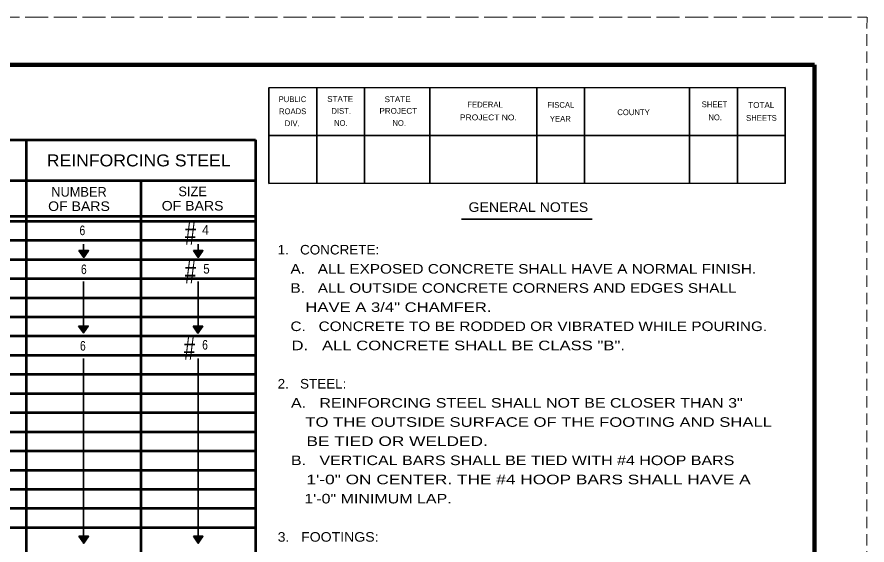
# Model space of a CAD drawing. Extents: x -560 to 120, y 26 to 466.
# Drawn here: x -57.5 to 120.2, y 355.5 to 465.8 of the extents above; entities that cross this region are included whole.
import ezdxf
from ezdxf.enums import TextEntityAlignment as Align

# ---------------------------------------------------------------- set-up
doc = ezdxf.new("R2010")
doc.units = 0
doc.header["$LTSCALE"] = 0.8
doc.linetypes.add('LONG_DASHED', pattern=[7.5, 6, -1.5])
doc.linetypes.add('MEDIUM_DASHED', pattern=[4.5, 3, -1.5])
doc.layers.add('1', color=7, linetype='Continuous', lineweight=53)
doc.layers.add('61', color=7, linetype='Continuous', lineweight=35)

msp = doc.modelspace()

# ---------------------------------------------------------------- linework, layer by layer
at = {"layer": '1', "linetype": 'MEDIUM_DASHED', "lineweight": 13}
msp.add_line((120.2391, 465.8427), (120.2191, 25.8227), dxfattribs=at)
at = {"layer": '1'}
for p, q in [((-127.5876, 440.21), (-7.5954, 440.21)), ((-55.5954, 440.21), (-55.5954, 267.21)), ((-7.5954, 440.21), (-7.5954, 267.21)), ((-127.5954, 431.71), (-7.5954, 431.71)), ((-31.5954, 431.71), (-31.5954, 267.21)), ((-267.5954, 424.21), (-7.6086, 424.21)), ((-267.5954, 423.21), (-7.6086, 423.21)), ((-267.5954, 419.21), (-7.6086, 419.21)), ((-267.5954, 415.21), (-7.6086, 415.21)), ((-267.5954, 411.21), (-7.6086, 411.21)), ((-267.5954, 407.21), (-7.6086, 407.21)), ((-267.5954, 403.21), (-7.6086, 403.21)), ((-267.5954, 399.21), (-7.6086, 399.21)), ((-267.5954, 395.21), (-7.6086, 395.21)), ((-267.5954, 391.21), (-7.6086, 391.21)), ((-267.5954, 387.21), (-7.6086, 387.21)), ((-267.5954, 383.21), (-7.6086, 383.21)), ((-267.5954, 379.21), (-7.6086, 379.21)), ((-267.5954, 375.21), (-7.6086, 375.21)), ((-267.5954, 371.21), (-7.6086, 371.21)), ((-267.5954, 367.21), (-7.6086, 367.21)), ((-267.5954, 363.21), (-7.6086, 363.21)), ((-267.5954, 359.21), (-7.6086, 359.21))]:
    msp.add_line(p, q, dxfattribs=at)
at = {"layer": '1', "lineweight": 35}
for p, q in [((35.464, 423.6132), (62.8017, 423.6132)), ((-43.5954, 418.4196), (-43.5954, 415.9432)), ((-19.5954, 418.4196), (-19.5954, 415.9432)), ((-43.5954, 410.5774), (-43.5954, 399.846)), ((-19.5954, 410.5774), (-19.5954, 399.846)), ((-43.5954, 394.4803), (-43.5954, 355.8888)), ((-19.5954, 394.4803), (-19.5954, 355.8888))]:
    msp.add_line(p, q, dxfattribs=at)
for points in [[(-44.5178, 417.0657), (-42.5178, 417.0657), (-43.5178, 415.6132)], [(-20.5897, 417.0657), (-18.5897, 417.0657), (-19.5897, 415.6132)], [(-44.5858, 401.2948), (-42.5858, 401.2948), (-43.5858, 399.8424)], [(-20.6576, 401.2268), (-18.6576, 401.2268), (-19.6576, 399.7744)], [(-44.5178, 357.381), (-42.5178, 357.381), (-43.5178, 355.9286)], [(-20.5896, 357.381), (-18.5896, 357.381), (-19.5896, 355.9286)]]:
    msp.add_lwpolyline(points, close=True, dxfattribs=at)
for points in [[(-44.3309, 416.9224), (-44.025, 416.9564), (-43.5492, 416.8545), (-43.2092, 416.9224), (-43.0733, 416.9224), (-42.8693, 416.9904), (-42.7334, 416.9564), (-43.3452, 416.8205), (-43.6171, 417.0584), (-43.5832, 416.8205), (-43.5832, 416.8885), (-43.2772, 416.9904), (-42.9033, 416.9904), (-42.9713, 416.9224), (-43.6851, 416.9564), (-43.957, 416.9224), (-44.1269, 416.8545), (-43.991, 416.7525), (-43.923, 416.6166), (-43.855, 416.4806), (-43.8211, 416.3787), (-43.7191, 416.2427), (-43.4132, 416.0048), (-43.4132, 415.8008), (-43.5152, 416.0048), (-43.5832, 416.1747), (-43.7191, 416.3447), (-43.855, 416.5146), (-44.059, 416.6845), (-44.1949, 416.9224), (-44.059, 416.7185), (-43.991, 416.4806), (-43.889, 416.3447), (-43.8211, 416.2767), (-43.6511, 416.1747), (-43.5492, 416.1067), (-43.4812, 415.9708), (-43.4472, 415.9367), (-43.5492, 415.9708), (-43.6511, 416.1407), (-43.6511, 415.9708), (-43.2772, 416.0727), (-42.7674, 416.9564), (-42.7334, 416.9564), (-42.7674, 416.8205), (-42.9033, 416.5826), (-43.0393, 416.3787), (-43.0733, 416.3787), (-43.2092, 416.1407), (-43.3113, 415.9367), (-43.4132, 415.8008), (-43.4812, 415.8008), (-42.6994, 416.9564), (-42.7334, 416.8545), (-42.6314, 416.9224), (-42.7674, 416.7525), (-42.9713, 416.5146), (-43.0733, 416.4466), (-43.2092, 416.2087), (-43.2772, 416.1747), (-43.3792, 416.3107), (-43.5152, 416.3107), (-43.6511, 416.3107), (-43.4132, 416.1067), (-43.4472, 416.2087), (-43.6171, 416.1067), (-43.2772, 416.5486), (-43.3452, 416.4126), (-43.3792, 416.3447), (-43.5152, 416.3447), (-43.6511, 416.4466), (-43.6851, 416.6505), (-43.7531, 416.7185), (-43.8211, 416.7865), (-43.4812, 416.8885), (-43.3452, 416.6845), (-43.3113, 416.7525), (-43.5832, 416.6166), (-43.4132, 416.6505), (-43.2092, 416.7865), (-43.1412, 416.7185), (-43.3792, 416.5146), (-43.3792, 416.7185), (-43.5152, 416.8545), (-43.8211, 416.7525), (-43.889, 416.3447), (-43.4812, 416.6845), (-43.3113, 416.6505), (-43.2092, 416.7185), (-43.1073, 416.8205), (-43.2432, 416.4806), (-43.2772, 416.2767), (-43.0393, 416.5826), (-43.2092, 416.5486), (-43.0053, 416.8205), (-43.1073, 416.6845), (-43.1412, 416.6505), (-43.3452, 416.4466), (-43.3792, 416.4806), (-43.4472, 416.6166), (-43.4812, 416.7865)], [(-43.4812, 416.7865), (-43.7191, 416.6166), (-43.5832, 416.5146), (-43.991, 416.7525), (-43.991, 416.8205), (-43.7871, 416.4806), (-43.4472, 416.5146), (-43.6171, 416.4126), (-43.4132, 416.4466), (-43.1073, 416.7525), (-42.9373, 416.7865), (-42.9373, 416.8205), (-43.0393, 416.6166), (-43.3452, 416.2427), (-43.4132, 415.9708), (-43.923, 416.7865), (-43.923, 416.9224), (-43.855, 416.7865), (-43.923, 416.3787), (-43.5492, 416.1747), (-43.6851, 415.8348), (-43.5152, 415.9027), (-43.6511, 416.3447), (-43.2092, 416.7865), (-43.5832, 416.6845)], [(-20.4028, 416.9224), (-20.0968, 416.9564), (-19.621, 416.8545), (-19.2811, 416.9224), (-19.1452, 416.9224), (-18.9412, 416.9904), (-18.8053, 416.9564), (-19.417, 416.8205), (-19.6889, 417.0584), (-19.655, 416.8205), (-19.655, 416.8885), (-19.3491, 416.9904), (-18.9752, 416.9904), (-19.0432, 416.9224), (-19.7569, 416.9564), (-20.0288, 416.9224), (-20.1988, 416.8545), (-20.0628, 416.7525), (-19.9948, 416.6166), (-19.9268, 416.4806), (-19.8929, 416.3787), (-19.7909, 416.2427), (-19.485, 416.0048), (-19.485, 415.8008), (-19.587, 416.0048), (-19.655, 416.1747), (-19.7909, 416.3447), (-19.9268, 416.5146), (-20.1308, 416.6845), (-20.2667, 416.9224), (-20.1308, 416.7185), (-20.0628, 416.4806), (-19.9608, 416.3447), (-19.8929, 416.2767), (-19.7229, 416.1747), (-19.621, 416.1067), (-19.553, 415.9708), (-19.519, 415.9367), (-19.621, 415.9708), (-19.7229, 416.1407), (-19.7229, 415.9708), (-19.3491, 416.0727), (-18.8392, 416.9564), (-18.8053, 416.9564), (-18.8392, 416.8205), (-18.9752, 416.5826), (-19.1112, 416.3787), (-19.1452, 416.3787), (-19.2811, 416.1407), (-19.3831, 415.9367), (-19.485, 415.8008), (-19.553, 415.8008), (-18.7712, 416.9564), (-18.8053, 416.8545), (-18.7033, 416.9224), (-18.8392, 416.7525), (-19.0432, 416.5146), (-19.1452, 416.4466), (-19.2811, 416.2087), (-19.3491, 416.1747), (-19.451, 416.3107), (-19.587, 416.3107), (-19.7229, 416.3107), (-19.485, 416.1067), (-19.519, 416.2087), (-19.6889, 416.1067), (-19.3491, 416.5486), (-19.417, 416.4126), (-19.451, 416.3447), (-19.587, 416.3447), (-19.7229, 416.4466), (-19.7569, 416.6505), (-19.8249, 416.7185), (-19.8929, 416.7865), (-19.553, 416.8885), (-19.417, 416.6845), (-19.3831, 416.7525), (-19.655, 416.6166), (-19.485, 416.6505), (-19.2811, 416.7865), (-19.2131, 416.7185), (-19.451, 416.5146), (-19.451, 416.7185), (-19.587, 416.8545), (-19.8929, 416.7525), (-19.9608, 416.3447), (-19.553, 416.6845), (-19.3831, 416.6505), (-19.2811, 416.7185), (-19.1791, 416.8205), (-19.3151, 416.4806), (-19.3491, 416.2767), (-19.1112, 416.5826), (-19.2811, 416.5486), (-19.0772, 416.8205), (-19.1791, 416.6845), (-19.2131, 416.6505), (-19.417, 416.4466), (-19.451, 416.4806), (-19.519, 416.6166), (-19.553, 416.7865)], [(-19.553, 416.7865), (-19.7909, 416.6166), (-19.655, 416.5146), (-20.0628, 416.7525), (-20.0628, 416.8205), (-19.8589, 416.4806), (-19.519, 416.5146), (-19.6889, 416.4126), (-19.485, 416.4466), (-19.1791, 416.7525), (-19.0092, 416.7865), (-19.0092, 416.8205), (-19.1112, 416.6166), (-19.417, 416.2427), (-19.485, 415.9708), (-19.9948, 416.7865), (-19.9948, 416.9224), (-19.9268, 416.7865), (-19.9948, 416.3787), (-19.621, 416.1747), (-19.7569, 415.8348), (-19.587, 415.9027), (-19.7229, 416.3447), (-19.2811, 416.7865), (-19.655, 416.6845)], [(-44.3989, 401.1516), (-44.093, 401.1856), (-43.6172, 401.0837), (-43.2772, 401.1516), (-43.1413, 401.1516), (-42.9373, 401.2196), (-42.8014, 401.1856), (-43.4132, 401.0497), (-43.6851, 401.2876), (-43.6512, 401.0497), (-43.6512, 401.1177), (-43.3453, 401.2196), (-42.9713, 401.2196), (-43.0393, 401.1516), (-43.7531, 401.1856), (-44.025, 401.1516), (-44.1949, 401.0837), (-44.059, 400.9817), (-43.991, 400.8458), (-43.923, 400.7097), (-43.8891, 400.6078), (-43.7871, 400.4718), (-43.4812, 400.2339), (-43.4812, 400.03), (-43.5832, 400.2339), (-43.6512, 400.4038), (-43.7871, 400.5738), (-43.923, 400.7437), (-44.127, 400.9137), (-44.2629, 401.1516), (-44.127, 400.9477), (-44.059, 400.7097), (-43.957, 400.5738), (-43.8891, 400.5058), (-43.7191, 400.4038), (-43.6172, 400.3359), (-43.5492, 400.1999), (-43.5152, 400.1659), (-43.6172, 400.1999), (-43.7191, 400.3698), (-43.7191, 400.1999), (-43.3453, 400.3019), (-42.8354, 401.1856), (-42.8014, 401.1856), (-42.8354, 401.0497), (-42.9713, 400.8117), (-43.1073, 400.6078), (-43.1413, 400.6078), (-43.2772, 400.3698), (-43.3792, 400.1659), (-43.4812, 400.03), (-43.5492, 400.03), (-42.7674, 401.1856), (-42.8014, 401.0837), (-42.6994, 401.1516), (-42.8354, 400.9817), (-43.0393, 400.7437), (-43.1413, 400.6757), (-43.2772, 400.4378), (-43.3453, 400.4038), (-43.4472, 400.5398), (-43.5832, 400.5398), (-43.7191, 400.5398), (-43.4812, 400.3359), (-43.5152, 400.4378), (-43.6851, 400.3359), (-43.3453, 400.7777), (-43.4132, 400.6418), (-43.4472, 400.5738), (-43.5832, 400.5738), (-43.7191, 400.6757), (-43.7531, 400.8797), (-43.8211, 400.9477), (-43.8891, 401.0157), (-43.5492, 401.1177), (-43.4132, 400.9137), (-43.3792, 400.9817), (-43.6512, 400.8458), (-43.4812, 400.8797), (-43.2772, 401.0157), (-43.2092, 400.9477), (-43.4472, 400.7437), (-43.4472, 400.9477), (-43.5832, 401.0837), (-43.8891, 400.9817), (-43.957, 400.5738), (-43.5492, 400.9137), (-43.3792, 400.8797), (-43.2772, 400.9477), (-43.1752, 401.0497), (-43.3113, 400.7097), (-43.3453, 400.5058), (-43.1073, 400.8117), (-43.2772, 400.7777), (-43.0733, 401.0497), (-43.1752, 400.9137), (-43.2092, 400.8797), (-43.4132, 400.6757), (-43.4472, 400.7097), (-43.5152, 400.8458), (-43.5492, 401.0157)], [(-43.5492, 401.0157), (-43.7871, 400.8458), (-43.6512, 400.7437), (-44.059, 400.9817), (-44.059, 401.0497), (-43.8551, 400.7097), (-43.5152, 400.7437), (-43.6851, 400.6418), (-43.4812, 400.6757), (-43.1752, 400.9817), (-43.0053, 401.0157), (-43.0053, 401.0497), (-43.1073, 400.8458), (-43.4132, 400.4718), (-43.4812, 400.1999), (-43.991, 401.0157), (-43.991, 401.1516), (-43.923, 401.0157), (-43.991, 400.6078), (-43.6172, 400.4038), (-43.7531, 400.064), (-43.5832, 400.1319), (-43.7191, 400.5738), (-43.2772, 401.0157), (-43.6512, 400.9137)], [(-20.4707, 401.0836), (-20.1647, 401.1176), (-19.6889, 401.0157), (-19.349, 401.0836), (-19.2131, 401.0836), (-19.0091, 401.1516), (-18.8732, 401.1176), (-19.4849, 400.9817), (-19.7568, 401.2196), (-19.7229, 400.9817), (-19.7229, 401.0497), (-19.417, 401.1516), (-19.0431, 401.1516), (-19.1111, 401.0836), (-19.8248, 401.1176), (-20.0968, 401.0836), (-20.2667, 401.0157), (-20.1307, 400.9137), (-20.0627, 400.7777), (-19.9947, 400.6418), (-19.9608, 400.5398), (-19.8588, 400.4038), (-19.5529, 400.1659), (-19.5529, 399.962), (-19.6549, 400.1659), (-19.7229, 400.3358), (-19.8588, 400.5058), (-19.9947, 400.6757), (-20.1988, 400.8457), (-20.3347, 401.0836), (-20.1988, 400.8797), (-20.1307, 400.6418), (-20.0287, 400.5058), (-19.9608, 400.4378), (-19.7908, 400.3358), (-19.6889, 400.2679), (-19.6209, 400.1319), (-19.5869, 400.0979), (-19.6889, 400.1319), (-19.7908, 400.3018), (-19.7908, 400.1319), (-19.417, 400.2339), (-18.9072, 401.1176), (-18.8732, 401.1176), (-18.9072, 400.9817), (-19.0431, 400.7437), (-19.1791, 400.5398), (-19.2131, 400.5398), (-19.349, 400.3018), (-19.451, 400.0979), (-19.5529, 399.962), (-19.6209, 399.962), (-18.8392, 401.1176), (-18.8732, 401.0157), (-18.7712, 401.0836), (-18.9072, 400.9137), (-19.1111, 400.6757), (-19.2131, 400.6078), (-19.349, 400.3698), (-19.417, 400.3358), (-19.5189, 400.4718), (-19.6549, 400.4718), (-19.7908, 400.4718), (-19.5529, 400.2679), (-19.5869, 400.3698), (-19.7568, 400.2679), (-19.417, 400.7097), (-19.4849, 400.5737), (-19.5189, 400.5058), (-19.6549, 400.5058), (-19.7908, 400.6078), (-19.8248, 400.8117), (-19.8928, 400.8797), (-19.9608, 400.9477), (-19.6209, 401.0497), (-19.4849, 400.8457), (-19.451, 400.9137), (-19.7229, 400.7777), (-19.5529, 400.8117), (-19.349, 400.9477), (-19.281, 400.8797), (-19.5189, 400.6757), (-19.5189, 400.8797), (-19.6549, 401.0157), (-19.9608, 400.9137), (-20.0287, 400.5058), (-19.6209, 400.8457), (-19.451, 400.8117), (-19.349, 400.8797), (-19.247, 400.9817), (-19.383, 400.6418), (-19.417, 400.4378), (-19.1791, 400.7437), (-19.349, 400.7097), (-19.1451, 400.9817), (-19.247, 400.8457), (-19.281, 400.8117), (-19.4849, 400.6078), (-19.5189, 400.6418), (-19.5869, 400.7777), (-19.6209, 400.9477)], [(-19.6209, 400.9477), (-19.8588, 400.7777), (-19.7229, 400.6757), (-20.1307, 400.9137), (-20.1307, 400.9817), (-19.9268, 400.6418), (-19.5869, 400.6757), (-19.7568, 400.5737), (-19.5529, 400.6078), (-19.247, 400.9137), (-19.0771, 400.9477), (-19.0771, 400.9817), (-19.1791, 400.7777), (-19.4849, 400.4038), (-19.5529, 400.1319), (-20.0627, 400.9477), (-20.0627, 401.0836), (-19.9947, 400.9477), (-20.0627, 400.5398), (-19.6889, 400.3358), (-19.8248, 399.996), (-19.6549, 400.0639), (-19.7908, 400.5058), (-19.349, 400.9477), (-19.7229, 400.8457)], [(-44.3309, 357.2378), (-44.025, 357.2717), (-43.5492, 357.1698), (-43.2092, 357.2378), (-43.0733, 357.2378), (-42.8693, 357.3057), (-42.7334, 357.2717), (-43.3452, 357.1358), (-43.6171, 357.3737), (-43.5832, 357.1358), (-43.5832, 357.2038), (-43.2772, 357.3057), (-42.9033, 357.3057), (-42.9713, 357.2378), (-43.6851, 357.2717), (-43.957, 357.2378), (-44.1269, 357.1698), (-43.991, 357.0678), (-43.923, 356.9319), (-43.855, 356.7959), (-43.8211, 356.694), (-43.7191, 356.558), (-43.4132, 356.3201), (-43.4132, 356.1162), (-43.5152, 356.3201), (-43.5832, 356.49), (-43.7191, 356.66), (-43.855, 356.8299), (-44.059, 356.9998), (-44.1949, 357.2378), (-44.059, 357.0338), (-43.991, 356.7959), (-43.889, 356.66), (-43.8211, 356.592), (-43.6511, 356.49), (-43.5492, 356.4221), (-43.4812, 356.2861), (-43.4472, 356.2521), (-43.5492, 356.2861), (-43.6511, 356.456), (-43.6511, 356.2861), (-43.2772, 356.3881), (-42.7674, 357.2717), (-42.7334, 357.2717), (-42.7674, 357.1358), (-42.9033, 356.8979), (-43.0393, 356.694), (-43.0733, 356.694), (-43.2092, 356.456), (-43.3113, 356.2521), (-43.4132, 356.1162), (-43.4812, 356.1162), (-42.6994, 357.2717), (-42.7334, 357.1698), (-42.6314, 357.2378), (-42.7674, 357.0678), (-42.9713, 356.8299), (-43.0733, 356.7619), (-43.2092, 356.524), (-43.2772, 356.49), (-43.3792, 356.626), (-43.5152, 356.626), (-43.6511, 356.626), (-43.4132, 356.4221), (-43.4472, 356.524), (-43.6171, 356.4221), (-43.2772, 356.8639), (-43.3452, 356.7279), (-43.3792, 356.66), (-43.5152, 356.66), (-43.6511, 356.7619), (-43.6851, 356.9658), (-43.7531, 357.0338), (-43.8211, 357.1018), (-43.4812, 357.2038), (-43.3452, 356.9998), (-43.3113, 357.0678), (-43.5832, 356.9319), (-43.4132, 356.9658), (-43.2092, 357.1018), (-43.1412, 357.0338), (-43.3792, 356.8299), (-43.3792, 357.0338), (-43.5152, 357.1698), (-43.8211, 357.0678), (-43.889, 356.66), (-43.4812, 356.9998), (-43.3113, 356.9658), (-43.2092, 357.0338), (-43.1073, 357.1358), (-43.2432, 356.7959), (-43.2772, 356.592), (-43.0393, 356.8979), (-43.2092, 356.8639), (-43.0053, 357.1358), (-43.1073, 356.9998), (-43.1412, 356.9658), (-43.3452, 356.7619), (-43.3792, 356.7959), (-43.4472, 356.9319), (-43.4812, 357.1018)], [(-43.4812, 357.1018), (-43.7191, 356.9319), (-43.5832, 356.8299), (-43.991, 357.0678), (-43.991, 357.1358), (-43.7871, 356.7959), (-43.4472, 356.8299), (-43.6171, 356.7279), (-43.4132, 356.7619), (-43.1073, 357.0678), (-42.9373, 357.1018), (-42.9373, 357.1358), (-43.0393, 356.9319), (-43.3452, 356.558), (-43.4132, 356.2861), (-43.923, 357.1018), (-43.923, 357.2378), (-43.855, 357.1018), (-43.923, 356.694), (-43.5492, 356.49), (-43.6851, 356.1502), (-43.5152, 356.2181), (-43.6511, 356.66), (-43.2092, 357.1018), (-43.5832, 356.9998)], [(-20.4027, 357.2378), (-20.0968, 357.2717), (-19.6209, 357.1698), (-19.281, 357.2378), (-19.1451, 357.2378), (-18.9411, 357.3057), (-18.8052, 357.2717), (-19.4169, 357.1358), (-19.6888, 357.3737), (-19.6549, 357.1358), (-19.6549, 357.2038), (-19.349, 357.3057), (-18.9751, 357.3057), (-19.0431, 357.2378), (-19.7568, 357.2717), (-20.0287, 357.2378), (-20.1987, 357.1698), (-20.0627, 357.0678), (-19.9947, 356.9319), (-19.9267, 356.7959), (-19.8928, 356.694), (-19.7908, 356.558), (-19.4849, 356.3201), (-19.4849, 356.1162), (-19.5869, 356.3201), (-19.6549, 356.49), (-19.7908, 356.66), (-19.9267, 356.8299), (-20.1307, 356.9998), (-20.2667, 357.2378), (-20.1307, 357.0338), (-20.0627, 356.7959), (-19.9608, 356.66), (-19.8928, 356.592), (-19.7228, 356.49), (-19.6209, 356.4221), (-19.5529, 356.2861), (-19.5189, 356.2521), (-19.6209, 356.2861), (-19.7228, 356.456), (-19.7228, 356.2861), (-19.349, 356.3881), (-18.8392, 357.2717), (-18.8052, 357.2717), (-18.8392, 357.1358), (-18.9751, 356.8979), (-19.1111, 356.694), (-19.1451, 356.694), (-19.281, 356.456), (-19.383, 356.2521), (-19.4849, 356.1162), (-19.5529, 356.1162), (-18.7712, 357.2717), (-18.8052, 357.1698), (-18.7032, 357.2378), (-18.8392, 357.0678), (-19.0431, 356.8299), (-19.1451, 356.7619), (-19.281, 356.524), (-19.349, 356.49), (-19.4509, 356.626), (-19.5869, 356.626), (-19.7228, 356.626), (-19.4849, 356.4221), (-19.5189, 356.524), (-19.6888, 356.4221), (-19.349, 356.8639), (-19.4169, 356.7279), (-19.4509, 356.66), (-19.5869, 356.66), (-19.7228, 356.7619), (-19.7568, 356.9658), (-19.8248, 357.0338), (-19.8928, 357.1018), (-19.5529, 357.2038), (-19.4169, 356.9998), (-19.383, 357.0678), (-19.6549, 356.9319), (-19.4849, 356.9658), (-19.281, 357.1018), (-19.213, 357.0338), (-19.4509, 356.8299), (-19.4509, 357.0338), (-19.5869, 357.1698), (-19.8928, 357.0678), (-19.9608, 356.66), (-19.5529, 356.9998), (-19.383, 356.9658), (-19.281, 357.0338), (-19.179, 357.1358), (-19.315, 356.7959), (-19.349, 356.592), (-19.1111, 356.8979), (-19.281, 356.8639), (-19.0771, 357.1358), (-19.179, 356.9998), (-19.213, 356.9658), (-19.4169, 356.7619), (-19.4509, 356.7959), (-19.5189, 356.9319), (-19.5529, 357.1018)], [(-19.5529, 357.1018), (-19.7908, 356.9319), (-19.6549, 356.8299), (-20.0627, 357.0678), (-20.0627, 357.1358), (-19.8588, 356.7959), (-19.5189, 356.8299), (-19.6888, 356.7279), (-19.4849, 356.7619), (-19.179, 357.0678), (-19.0091, 357.1018), (-19.0091, 357.1358), (-19.1111, 356.9319), (-19.4169, 356.558), (-19.4849, 356.2861), (-19.9947, 357.1018), (-19.9947, 357.2378), (-19.9267, 357.1018), (-19.9947, 356.694), (-19.6209, 356.49), (-19.7568, 356.1502), (-19.5869, 356.2181), (-19.7228, 356.66), (-19.281, 357.1018), (-19.6549, 356.9998)]]:
    msp.add_lwpolyline(points, dxfattribs=at)
at = {"layer": '61', "linetype": 'LONG_DASHED', "lineweight": 13}
msp.add_line((-559.7809, 465.8427), (120.2391, 465.8427), dxfattribs=at)
at = {"layer": '61', "lineweight": 158}
msp.add_line((109.2591, 455.8427), (109.2791, 35.8027), dxfattribs=at)
at = {"layer": '61'}
for p, q in [((5.1791, 451.0827), (5.1791, 431.0827)), ((15.1791, 451.0827), (15.1791, 431.0827)), ((28.8591, 451.0827), (28.8591, 431.0827)), ((51.1791, 451.0827), (51.1791, 431.0827)), ((61.1791, 451.0827), (61.1791, 431.0827)), ((83.1591, 451.1027), (83.1591, 431.1027)), ((93.1591, 451.1027), (93.1591, 431.1027)), ((103.1791, 441.0627), (-4.8409, 441.0827))]:
    msp.add_line(p, q, dxfattribs=at)
at = {"layer": '61', "lineweight": 158}
msp.add_lwpolyline([(109.2591, 455.8427), (-529.7809, 455.8427), (-529.7809, 35.8227)], dxfattribs=at)
at = {"layer": '61'}
for points in [[(103.1591, 451.1027), (-4.8209, 451.0827), (-4.8209, 431.0827)], [(103.1591, 451.1027), (103.1591, 431.1027), (-4.8209, 431.0827)]]:
    msp.add_lwpolyline(points, dxfattribs=at)

# ---------------------------------------------------------------- texts
at = {"layer": '1'}
for s, height, width, p in [('REINFORCING STEEL', 2.5, 1.1, (-51.2414, 434.6382)), ('GENERAL NOTES', 2, 1.1, (36.9344, 425.1347)), ('1.   CONCRETE:', 2, 1.05, (-2.9781, 416.233)), ('   A.   ALL EXPOSED CONCRETE SHALL HAVE A NORMAL FINISH.', 2, 1.2, (-2.9781, 412.233)), ('   B.   ALL OUTSIDE CONCRETE CORNERS AND EDGES SHALL', 2, 1.2, (-2.9781, 408.233)), ('      HAVE A 3/4" CHAMFER.', 2, 1.3, (-2.9781, 404.233)), ('   C.   CONCRETE TO BE RODDED OR VIBRATED WHILE POURING.', 2, 1.2, (-2.9781, 400.233)), ('   D.   ALL CONCRETE SHALL BE CLASS "B".', 2, 1.3, (-2.9781, 396.233)), ('2.   STEEL:', 2, 1.05, (-2.9781, 388.233)), ('   A.   REINFORCING STEEL SHALL NOT BE CLOSER THAN 3"', 2, 1.25, (-2.9781, 384.233)), ('      TO THE OUTSIDE SURFACE OF THE FOOTING AND SHALL', 2, 1.3, (-2.9781, 380.233)), ('      BE TIED OR WELDED.', 2, 1.35, (-2.9781, 376.233)), ('   B.   VERTICAL BARS SHALL BE TIED WITH #4 HOOP BARS', 2, 1.25, (-2.9781, 372.233)), ('      1\'-0" ON CENTER. THE #4 HOOP BARS SHALL HAVE A', 2, 1.35, (-2.9781, 368.233)), ('      1\'-0" MINIMUM LAP.', 2, 1.25, (-2.9781, 364.233)), ('3.   FOOTINGS:', 2, 1.1, (-2.9781, 356.233))]:
    msp.add_text(s, height=height, dxfattribs=dict(at, width=width)).set_placement(p)
for s, p in [('NUMBER', (-44.5135, 428.3243)), ('SIZE', (-20.7615, 428.4174))]:
    msp.add_text(s, height=2, dxfattribs=at).set_placement(p, align=Align.CENTER)
for s, height, width, p in [('OF BARS', 2, 1.1, (-44.5136, 425.3243)), ('OF BARS', 2, 1.1, (-20.7615, 425.4174)), ('#', 4.8, 0.65, (-21.2165, 418.2694)), ('6', 2, 0.8, (-43.8099, 420.279)), ('4', 2, 0.95, (-18.0617, 420.3807)), ('6', 2, 0.8, (-43.5046, 412.1372)), ('#', 4.8, 0.65, (-21.2165, 410.2295)), ('5', 2, 0.9, (-17.8581, 412.239)), ('6', 2, 0.8, (-43.7081, 396.1592)), ('#', 4.8, 0.65, (-21.4201, 394.2514)), ('6', 2, 0.8, (-18.1635, 396.3628))]:
    msp.add_text(s, height=height, dxfattribs=dict(at, width=width)).set_placement(p, align=Align.CENTER)
at = {"layer": '61'}
for s, rotation, p in [('PUBLIC', 0.033, (-2.7809, 448.0627)), ('FEDERAL', 0.007, (36.6791, 446.9427)), ('FISCAL', 359.942, (53.4191, 446.8827)), ('SHEET', 0.059, (85.6791, 447.0027)), ('ROADS', 0.124, (-2.7009, 445.5428)), ('DIST.', 0.056, (8.2591, 445.6227)), ('COUNTY', 0.069, (68.0391, 445.3427)), ('YEAR', 0.105, (53.9391, 443.9828)), ('SHEETS', 359.959, (94.9591, 444.1627)), ('DIV.', 359.932, (-1.5009, 443.0428))]:
    msp.add_text(s, height=1.201, rotation=rotation, dxfattribs=at).set_placement(p)
for s, rotation, width, p in [('STATE', 0.059, 1.05, (7.3791, 448.1227)), ('STATE', 0.059, 1.05, (19.3791, 448.0627)), ('TOTAL', 359.926, 1.05, (95.4191, 446.8628)), ('PROJECT', 359.908, 1.05, (18.2991, 445.6427)), ('NO.', 359.852, 0.95, (8.8391, 443.1027)), ('NO.', 0.225, 0.95, (21.0391, 443.1027)), ('PROJECT NO.', 359.922, 1.1, (35.1391, 444.2827)), ('NO.', 359.852, 0.95, (87.0991, 444.2827))]:
    msp.add_text(s, height=1.201, rotation=rotation, dxfattribs=dict(at, width=width)).set_placement(p)

doc.saveas('drawing.dxf')
